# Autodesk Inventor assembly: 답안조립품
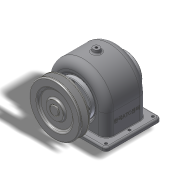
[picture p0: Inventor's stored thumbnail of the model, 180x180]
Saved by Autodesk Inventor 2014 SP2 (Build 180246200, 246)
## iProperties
Created: 2015-09
Part Number: 답안조립품
Document SubType Name: Assembly
Designer: 201-21
Author: 201-21
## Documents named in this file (14)
- C:\Users\201-21\Desktop\450907V1012\450907V1012\답안조립품.iam
- C:\Users\201-21\Desktop\450907V1012\450907V1012\본체.ipt
- C:\Users\201-21\Desktop\450907V1012\450907V1012\V-벨트풀리.ipt
- C:\Users\201-21\Desktop\450907V1012\450907V1012\뒤커버.ipt
- C:\Users\201-21\Desktop\450907V1012\450907V1012\멈춤나사 - M4x10.ipt
- C:\Users\201-21\Desktop\450907V1012\450907V1012\베어링 6203.ipt
- C:\Users\201-21\Desktop\450907V1012\450907V1012\볼트 M3 x 8.ipt
- C:\Users\201-21\Desktop\450907V1012\450907V1012\볼트 M3 x 10.ipt
- C:\Users\201-21\Desktop\450907V1012\450907V1012\스퍼기어.ipt
- C:\Users\201-21\Desktop\450907V1012\450907V1012\앞커버.ipt
- C:\Users\201-21\Desktop\450907V1012\450907V1012\오일 실 17 32 8.ipt
- C:\Users\201-21\Desktop\450907V1012\450907V1012\축.ipt
- C:\Users\201-21\Desktop\450907V1012\450907V1012\키 - 5 x 5 x 18.ipt
- C:\Users\201-21\Desktop\450907V1012\450907V1012\키 - 6 x 6 x 22.ipt
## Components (9 placed, 3 different names)
1. V-벨트풀리:1 — 각도:4
2. ISO 4762 M3 x 10:1
3. ISO 4762 M3 x 10:2
4. ISO 4762 M3 x 10:3
5. ISO 4762 M3 x 10:4
6. ISO 4762 M3 x 8:1
7. ISO 4762 M3 x 8:2
8. ISO 4762 M3 x 8:3
9. ISO 4762 M3 x 8:4
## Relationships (1: Angle 1)
- 각도:4 [Angle]: V-벨트풀리:1
